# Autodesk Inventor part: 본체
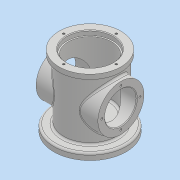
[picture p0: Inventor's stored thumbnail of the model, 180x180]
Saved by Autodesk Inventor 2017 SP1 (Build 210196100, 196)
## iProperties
Part Number: 본체
Material: 일반
Document SubType Name: Modeling
Designer: MRC
Density: 1 g/cm^3
Appearance: 기본값
Author: MRC
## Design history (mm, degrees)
sketch "스케치1"
  geometry: C1 r 40 at (0, 0); 1 further point
  constraints: 1 centre point, 1 coincident
  dimensions: "d0" = 80 diameter of C1
extrude "돌출1" new body sketch "스케치1" distance "d1" = 88; taper "d2" = 0 deg
sketch "스케치2"
  geometry: C1 r 55 at (0, 0); 1 further point
  constraints: 1 centre point, 1 coincident
  dimensions: "d3" = 110 diameter of C1
extrude "돌출2" join sketch "스케치2" distance "d4" = 10; taper "d5" = 0 deg
sketch "스케치5"
  geometry: C1 r 47 at (0, 0); 1 further point
  constraints: 1 centre point, 1 coincident
  dimensions: "d18" = 94 diameter of C1
extrude "돌출4" join sketch "스케치5" distance "d19" = 10; taper "d20" = 0 deg
hole "구멍2" diameter "d23" = 66; stored, may be unused: countersink angle "d27" = 90 deg, drill point angle "d29" = 0 deg; dims "d21" = 10, "d22" = 10, "d24" = 6, "d25" = 70, "d26" = 7, "d28" = 86
hole "구멍3" diameter "d32" = 10; stored, may be unused: countersink angle "d36" = 90 deg, drill point angle "d38" = 0 deg; dims "d30" = 10, "d31" = 10, "d33" = 6, "d34" = 66, "d35" = 16, "d37" = 86
node "작업 평면1"
sketch "스케치8"
  geometry: L1 (-55, -10)-(55, -10) reference; C1 r 35 at (0, 44); 1 further point
  constraints: 1 centre point, 1 vertical alignment
  dimensions: "d43" = 70 diameter of C1; "d44" = 54 distance from line of C1.centre L1
extrude "돌출5" join sketch "스케치8" stored distance "d45" = 94; taper "d46" = 0 deg
sketch "스케치9"
  geometry: C1 r 35 at (0, 0) reference; C2 r 24 at (0, 0); 1 further point
  constraints: 1 centre point, 1 coincident
  dimensions: "d47" = 48 diameter of C2
extrude "돌출6" cut sketch "스케치9" stored distance "d48" = 94; taper "d49" = 0 deg
sketch "스케치10"
  geometry: C1 r 24 at (0, 0) reference; 2 further points
  constraints: 1 vertical alignment
  dimensions: "d50" = 29 distance of point (0, -29) C1.centre
hole "구멍4" sketch "스케치10" at (0, -29) diameter "d51" = 3.242; stored, may be unused: countersink angle "d55" = 90 deg, drill point angle "d57" = 118 deg; dims "d52" = 6, "d53" = 12.24, "d54" = 3.58, "d56" = 8
node "작업 평면2"
sketch "스케치11"
  geometry: L1 (0, 57)-(0, 31); L2 (-7, 57)-(-7, 31); L3 (7, 31)-(7, 57); L4 (-55, -10)-(55, -10) reference; A1 r 7 centre (0, 57) between (7, 57) and (-7, 57); A2 r 7 centre (0, 31) between (-7, 31) and (7, 31); 2 further points
  constraints: 8 end point, 4 point on circle, 4 tangent, 2 centre point, 1 midpoint, 1 parallel, 1 vertical, 1 vertical alignment
  dimensions: "d62" = 40 dimension on A2 A1; "d63" = 54 distance from line of point (0, 44) L4; "d77" = 7 radius of A1
extrude "돌출7" join sketch "스케치11" stored distance "d64" = 94; taper "d65" = 15 deg
sketch "스케치12"
  geometry: L1 (7, -57)-(7, -31) reference; L2 (-7, -31)-(-7, -57) reference; A1 r 7 centre (0, -31) between (7, -31) and (-7, -31) reference; A2 r 7 centre (0, -57) between (-7, -57) and (7, -57) reference; 3 further points
  constraints: 2 coincident
hole "구멍5" sketch "스케치12" at (0, -57), (0, -31) diameter "d66" = 4.134; stored, may be unused: countersink angle "d70" = 90 deg, drill point angle "d72" = 118 deg; dims "d67" = 6, "d68" = 12.24, "d69" = 3.58, "d71" = 8
sketch "스케치13"
  geometry: C1 r 50 at (0, 0); 1 further point
  constraints: 1 centre point, 1 coincident, 1 other
  dimensions: "d73" = 100 diameter of C1
feature "엠보싱1" sketch "스케치13" dims "d74" = 0.5, "d75" = 0
fillet "모깎기1" dims "d76" = 3
sketch "스케치14"
  geometry: 2 further points
  constraints: 1 vertical alignment
  dimensions: "d78" = 40 distance of point (0, -40) point (0, 0)
hole "구멍6" sketch "스케치14" at (0, -40) diameter "d79" = 3.242; stored, may be unused: countersink angle "d83" = 90 deg, drill point angle "d85" = 118 deg; dims "d80" = 6, "d81" = 12.24, "d82" = 3.58, "d84" = 8
chamfer "모따기1" distance "d89" = 1; stored, may be unused: second distance "d90" = 2, angle "d91" = 45 deg
fillet "모깎기2" dims "d95" = 3
node "솔리드1"
pattern_circular "원형 패턴1" dims angle "d59" = 360 deg
mirror "미러1"
pattern_circular "원형 패턴2" dims angle "d87" = 360 deg
node "투영된 루프1"
node "투영된 루프2"
other parameters: "d42" = 47, "d61" = 55
